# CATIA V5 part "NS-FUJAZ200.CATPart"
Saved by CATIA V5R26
Part number: NS-FUJAZ200
Bounding box of the stored display mesh (mm): x -70.94 to 158, y -249.867 to 0, z -71 to 71
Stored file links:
  R:\Document\坂尻\その他\ナベヤデータ変換\安全カバーキャスター\MCBJSAZ200\NS-FUJAZ200.CATPart
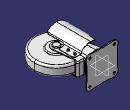
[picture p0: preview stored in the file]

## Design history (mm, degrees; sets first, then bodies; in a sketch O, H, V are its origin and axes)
Body1 (main body)
  Solid1: solid without history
